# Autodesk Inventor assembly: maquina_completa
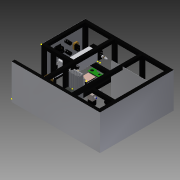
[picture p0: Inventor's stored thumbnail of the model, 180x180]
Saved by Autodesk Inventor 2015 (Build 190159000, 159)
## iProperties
Created: 2016-05
Part Number: maquina_completa
Document SubType Name: Assembly
Designer: Diego
Author: Diego
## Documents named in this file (23)
- C:\Users\Diego\Dropbox\UNIVERSIDAD\TFG\inventor\maquina_completa.iam
- C:\Users\Diego\Dropbox\UNIVERSIDAD\TFG\inventor\Estructura\estructura1.ipt
- C:\Users\Diego\Dropbox\UNIVERSIDAD\TFG\inventor\chapa_frontal.ipt
- C:\Users\Diego\Dropbox\UNIVERSIDAD\TFG\inventor\boton_2posiciones.ipt
- C:\Users\Diego\Dropbox\UNIVERSIDAD\TFG\inventor\piloto_rojo.ipt
- C:\Users\Diego\Dropbox\UNIVERSIDAD\TFG\inventor\seta_emergencia.ipt
- C:\Users\Diego\Dropbox\UNIVERSIDAD\TFG\inventor\TIRISTORES.ipt
- C:\Users\Diego\Dropbox\UNIVERSIDAD\TFG\inventor\Radiador.ipt
- C:\Users\Diego\Dropbox\UNIVERSIDAD\TFG\inventor\transformador.ipt
- C:\Users\Diego\Dropbox\UNIVERSIDAD\TFG\inventor\cilindro.ipt
- C:\Users\Diego\Dropbox\UNIVERSIDAD\TFG\inventor\portaelectrodo_abajo.ipt
- C:\Users\Diego\Dropbox\UNIVERSIDAD\TFG\inventor\separadores.ipt
- C:\Users\Diego\Dropbox\UNIVERSIDAD\TFG\inventor\fuente_24Vdc.ipt
- C:\Users\Diego\Dropbox\UNIVERSIDAD\TFG\inventor\imagenes\balda.ipt
- C:\Users\Diego\Dropbox\UNIVERSIDAD\TFG\inventor\electrovalvula_1.ipt
- C:\Users\Diego\Dropbox\UNIVERSIDAD\TFG\inventor\tapon_M6.ipt
- C:\Users\Diego\Dropbox\UNIVERSIDAD\TFG\inventor\electrovalvula_2.ipt
- C:\Users\Diego\Dropbox\UNIVERSIDAD\TFG\inventor\racor.ipt
- C:\Users\Diego\Dropbox\UNIVERSIDAD\TFG\inventor\regulador_filtro.ipt
- C:\Users\Diego\Dropbox\UNIVERSIDAD\TFG\inventor\regulador.ipt
- C:\Users\Diego\Dropbox\UNIVERSIDAD\TFG\inventor\snubber.ipt
- C:\Users\Diego\Dropbox\UNIVERSIDAD\TFG\inventor\LCD.ipt
- C:\Users\Diego\Dropbox\UNIVERSIDAD\TFG\inventor\teclado_matricial.ipt
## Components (38 placed, 22 different names)
1. estructura1:1 — Rígido:1, Rígido:6, Rígido:7, Rígido:8, Rígido:13, Nivelación:1, Rígido:16, Rígido:20, Rígido:23, Rígido:26, Rígido:27
2. chapa_frontal:1 — Rígido:1, Rígido:2, De rotación:1, De rotación:2, De rotación:3, Rígido:3, Rígido:4
3. boton_2posiciones:1 — Rígido:2
4. boton_2posiciones:2 — Rígido:3
5. piloto_rojo:1 — De rotación:2
6. piloto_rojo:2 — De rotación:1
7. piloto_rojo:3 — De rotación:3
8. seta_emergencia:1 — Rígido:4
9. TIRISTORES:1 — Rígido:5
10. Radiador:1 — Rígido:5, Rígido:6
11. transformador:1 — Rígido:7
12. cilindro:2 — Rígido:8, De rotación:4, Rígido:9, Rígido:10, Rígido:11, Rígido:12, Rígido:28, Rígido:29
13. portaelectrodo_abajo:1 — De rotación:4
14. separadores:1 — Rígido:10
15. separadores:2 — Rígido:9
16. separadores:3 — Rígido:12
17. separadores:4 — Rígido:11
18. fuente_24Vdc:1 — Rígido:13
19. balda:1 — Nivelación:1
20. tapon_M6:1 — De rotación:5
21. tapon_M6:2 — Rígido:14
22. electrovalvula_2:1 — De rotación:5, Rígido:14, Rígido:15, De rotación:6, De rotación:7, Rígido:16
23. racor:1 — De rotación:7
24. racor:2 — De rotación:6
25. racor:3 — Rígido:15
26. electrovalvula_1:1 — Rígido:17, Rígido:18, Rígido:19, Rígido:20
27. racor:4 — Rígido:18
28. racor:5 — Rígido:17
29. tapon_M6:3 — Rígido:19
30. regulador_filtro:2 — Rígido:21, Rígido:22, Rígido:23
31. racor:6 — Rígido:22
32. racor:7 — Rígido:21
33. regulador:1 — Rígido:24, Rígido:25, Rígido:26
34. racor:8 — Rígido:25
35. racor:9 — Rígido:24
36. snubber:1 — Rígido:27
37. LCD:1
38. teclado_matricial:1 — Rígido:29
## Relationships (37: WeldJoint 29, RevoluteJoint 7, Flush 1)
- Rígido:1 [WeldJoint]: estructura1:1 ↔ chapa_frontal:1
- Rígido:2 [WeldJoint]: chapa_frontal:1 ↔ boton_2posiciones:1
- De rotación:1 [RevoluteJoint]: chapa_frontal:1 ↔ piloto_rojo:2
- De rotación:2 [RevoluteJoint]: chapa_frontal:1 ↔ piloto_rojo:1
- De rotación:3 [RevoluteJoint]: chapa_frontal:1 ↔ piloto_rojo:3
- Rígido:3 [WeldJoint]: chapa_frontal:1 ↔ boton_2posiciones:2
- Rígido:4 [WeldJoint]: chapa_frontal:1 ↔ seta_emergencia:1
- Rígido:5 [WeldJoint]: TIRISTORES:1 ↔ Radiador:1
- Rígido:6 [WeldJoint]: estructura1:1 ↔ Radiador:1
- Rígido:7 [WeldJoint]: estructura1:1 ↔ transformador:1
- Rígido:8 [WeldJoint]: estructura1:1 ↔ cilindro:2
- De rotación:4 [RevoluteJoint]: cilindro:2 ↔ portaelectrodo_abajo:1
- Rígido:9 [WeldJoint]: cilindro:2 ↔ separadores:2
- Rígido:10 [WeldJoint]: cilindro:2 ↔ separadores:1
- Rígido:11 [WeldJoint]: cilindro:2 ↔ separadores:4
- Rígido:12 [WeldJoint]: cilindro:2 ↔ separadores:3
- Rígido:13 [WeldJoint]: estructura1:1 ↔ fuente_24Vdc:1
- Nivelación:1 [Flush]: estructura1:1 ↔ balda:1
- De rotación:5 [RevoluteJoint]: tapon_M6:1 ↔ electrovalvula_2:1
- Rígido:14 [WeldJoint]: tapon_M6:2 ↔ electrovalvula_2:1
- Rígido:15 [WeldJoint]: electrovalvula_2:1 ↔ racor:3
- De rotación:6 [RevoluteJoint]: electrovalvula_2:1 ↔ racor:2
- De rotación:7 [RevoluteJoint]: electrovalvula_2:1 ↔ racor:1
- Rígido:16 [WeldJoint]: estructura1:1 ↔ electrovalvula_2:1
- Rígido:17 [WeldJoint]: electrovalvula_1:1 ↔ racor:5
- Rígido:18 [WeldJoint]: electrovalvula_1:1 ↔ racor:4
- Rígido:19 [WeldJoint]: electrovalvula_1:1 ↔ tapon_M6:3
- Rígido:20 [WeldJoint]: estructura1:1 ↔ electrovalvula_1:1
- Rígido:21 [WeldJoint]: regulador_filtro:2 ↔ racor:7
- Rígido:22 [WeldJoint]: regulador_filtro:2 ↔ racor:6
- Rígido:23 [WeldJoint]: estructura1:1 ↔ regulador_filtro:2
- Rígido:24 [WeldJoint]: regulador:1 ↔ racor:9
- Rígido:25 [WeldJoint]: regulador:1 ↔ racor:8
- Rígido:26 [WeldJoint]: estructura1:1 ↔ regulador:1
- Rígido:27 [WeldJoint]: estructura1:1 ↔ snubber:1
- Rígido:28 [WeldJoint]: cilindro:2
- Rígido:29 [WeldJoint]: cilindro:2 ↔ teclado_matricial:1
